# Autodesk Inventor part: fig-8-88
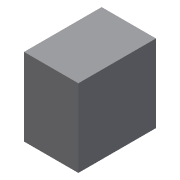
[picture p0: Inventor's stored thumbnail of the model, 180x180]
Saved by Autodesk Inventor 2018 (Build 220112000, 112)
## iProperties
Created: 2009-04
Part Number: fig-8-88
Document SubType Name: Modeling
Designer: Sham
Density: 1 g/cm^3
Material: Generic
Appearance: Default
Author: Sham
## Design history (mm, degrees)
sketch "Sketch5"
  geometry: L1 (14, -20)-(0, -20); L2 (0, -20)-(0, 0); L3 (0, 0)-(14, 0); L4 (14, 0)-(14, -20)
  constraints: 8 end point
extrude "Extrusion2" new body sketch "Sketch5" distance "d3" = 20; taper "d4" = 0 deg
sketch "Sketch6"
  geometry: L1 (-5, 12)-(17, 7)
  constraints: 2 end point
split "Split8" sketch "Sketch6"
  body "Solid2"
body "Solid3"
body "Solid4"
